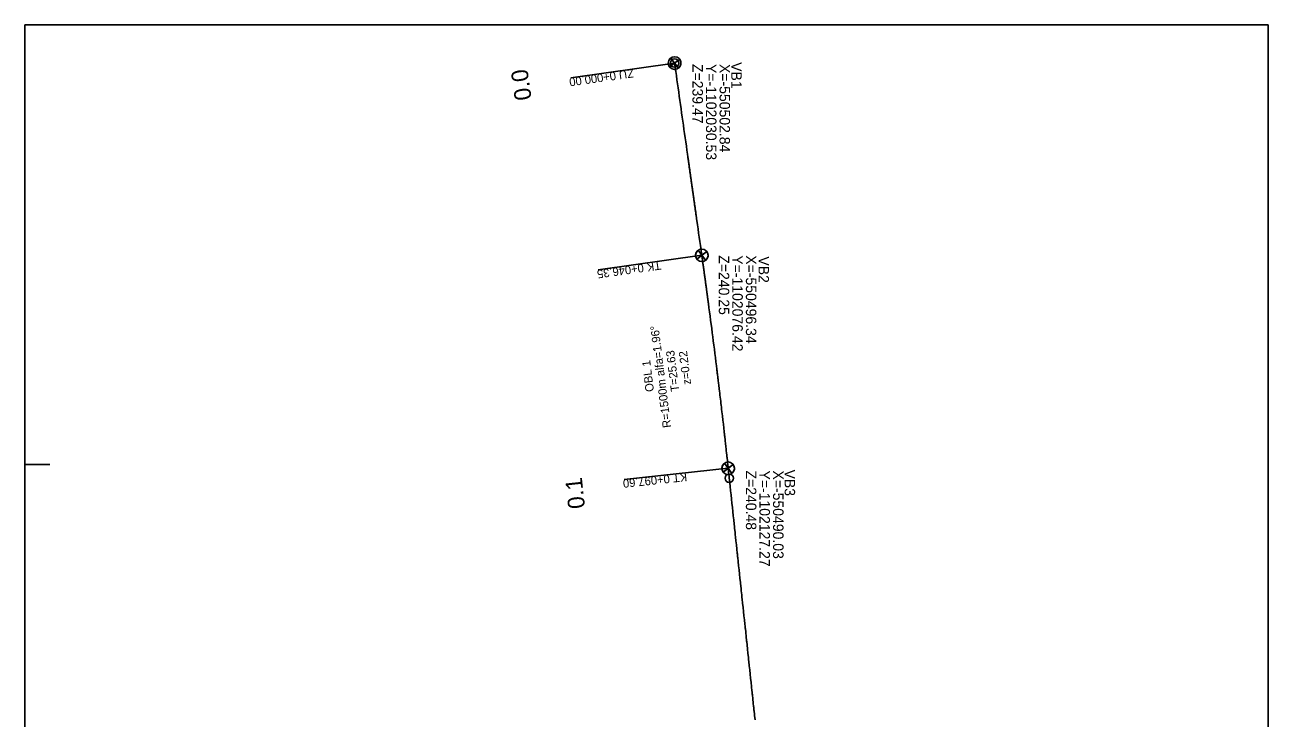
# Model space of a CAD drawing. Extents: x -583517 to -548566, y -1166112 to -1101582.
# Drawn here: x -550658.1 to -550361.1, y -1102186.9 to -1102021.4 of the extents above; entities that cross this region are included whole.
import ezdxf

# ---------------------------------------------------------------- set-up
doc = ezdxf.new("R2010")
doc.units = 0
for name, color, linetype in [('13', 7, 'Continuous'), ('59', 7, 'Continuous'), ('8', 7, 'Continuous'), ('Body pricny rez', 7, 'Continuous'), ('Popis PP', 7, 'Continuous'), ('Rámy', 7, 'Continuous')]:
    doc.layers.add(name, color=color, linetype=linetype)

msp = doc.modelspace()

# ---------------------------------------------------------------- linework, layer by layer
at = {"layer": '13'}
for points in [[(-550502.84, -1102030.53), (-550527.59, -1102034.03)], [(-550496.34, -1102076.42), (-550521.1, -1102079.92)], [(-550490.03, -1102127.27), (-550514.89, -1102129.93)]]:
    msp.add_lwpolyline(points, dxfattribs=at)
at = {"layer": '8'}
for p, q in [((-550501.63, -1102029.63), (-550504.04, -1102031.42)), ((-550503.73, -1102029.32), (-550501.94, -1102031.73)), ((-550502.84, -1102030.53), (-550503.73, -1102029.32)), ((-550502.84, -1102030.53), (-550503.73, -1102029.32)), ((-550501.63, -1102029.63), (-550502.84, -1102030.53)), ((-550504.04, -1102031.42), (-550502.84, -1102030.53)), ((-550504.04, -1102031.42), (-550502.84, -1102030.53)), ((-550502.84, -1102030.53), (-550501.94, -1102031.73)), ((-550495.14, -1102075.52), (-550497.55, -1102077.31)), ((-550497.55, -1102077.31), (-550496.34, -1102076.42)), ((-550497.55, -1102077.31), (-550496.34, -1102076.42)), ((-550496.34, -1102076.42), (-550497.24, -1102075.21)), ((-550496.34, -1102076.42), (-550497.24, -1102075.21)), ((-550497.24, -1102075.22), (-550495.45, -1102077.62)), ((-550495.14, -1102075.52), (-550496.34, -1102076.42)), ((-550496.34, -1102076.42), (-550495.45, -1102077.62)), ((-550491.24, -1102128.17), (-550490.03, -1102127.27)), ((-550491.24, -1102128.17), (-550490.03, -1102127.27)), ((-550488.83, -1102126.38), (-550491.23, -1102128.17)), ((-550490.93, -1102126.07), (-550489.14, -1102128.48)), ((-550490.03, -1102127.27), (-550490.93, -1102126.07)), ((-550490.03, -1102127.27), (-550490.93, -1102126.07)), ((-550488.83, -1102126.38), (-550490.03, -1102127.27)), ((-550490.03, -1102127.27), (-550489.14, -1102128.48))]:
    msp.add_line(p, q, dxfattribs=at)
for centre in [(-550502.84, -1102030.53), (-550496.34, -1102076.42), (-550490.03, -1102127.27)]:
    msp.add_circle(centre, 1.5, dxfattribs=at)
for centre, start, end in [((-550502.84, -1102030.53), 126.6271, 216.6271), ((-550502.84, -1102030.53), 126.6271, 216.6271), ((-550502.84, -1102030.53), 306.6271, 36.6271), ((-550496.34, -1102076.42), 126.6271, 216.6271), ((-550496.34, -1102076.42), 126.6271, 216.6271), ((-550496.34, -1102076.42), 306.6271, 36.6271), ((-550490.03, -1102127.27), 126.6271, 216.6271), ((-550490.03, -1102127.27), 126.6271, 216.6271), ((-550490.03, -1102127.27), 306.6271, 36.6271)]:
    msp.add_arc(centre, 1.5, start, end, dxfattribs=at)
at = {"layer": 'Body pricny rez'}
msp.add_lwpolyline([(-550502.84, -1102030.53), (-550502.7, -1102031.52), (-550502.56, -1102032.51), (-550502.42, -1102033.5), (-550502.28, -1102034.49), (-550502.14, -1102035.48), (-550502, -1102036.47), (-550501.86, -1102037.46), (-550501.72, -1102038.45), (-550501.72, -1102038.45), (-550501.58, -1102039.44), (-550501.44, -1102040.43), (-550501.3, -1102041.42), (-550501.16, -1102042.41), (-550501.02, -1102043.4), (-550500.88, -1102044.39), (-550500.74, -1102045.38), (-550500.6, -1102046.37), (-550500.46, -1102047.36), (-550500.32, -1102048.35), (-550500.17, -1102049.34), (-550500.03, -1102050.33), (-550499.89, -1102051.32), (-550499.75, -1102052.31), (-550499.67, -1102052.88), (-550499.64, -1102053.1), (-550499.61, -1102053.3), (-550499.61, -1102053.33), (-550499.58, -1102053.55), (-550499.55, -1102053.78), (-550499.52, -1102054), (-550499.48, -1102054.23), (-550499.47, -1102054.29), (-550499.45, -1102054.45), (-550499.42, -1102054.68), (-550499.39, -1102054.9), (-550499.36, -1102055.13), (-550499.33, -1102055.28), (-550499.32, -1102055.35), (-550499.29, -1102055.58), (-550499.26, -1102055.8), (-550499.23, -1102056.03), (-550499.2, -1102056.25), (-550499.19, -1102056.27), (-550499.16, -1102056.48), (-550499.13, -1102056.7), (-550499.1, -1102056.93), (-550499.07, -1102057.15), (-550499.05, -1102057.26), (-550499.04, -1102057.38), (-550499.01, -1102057.6), (-550498.97, -1102057.83), (-550498.94, -1102058.05), (-550498.91, -1102058.25), (-550498.91, -1102058.28), (-550498.88, -1102058.5), (-550498.85, -1102058.72), (-550498.81, -1102058.95), (-550498.78, -1102059.17), (-550498.77, -1102059.24), (-550498.75, -1102059.4), (-550498.72, -1102059.62), (-550498.69, -1102059.85), (-550498.66, -1102060.07), (-550498.63, -1102060.23), (-550498.62, -1102060.3), (-550498.59, -1102060.52), (-550498.56, -1102060.75), (-550498.53, -1102060.97), (-550498.5, -1102061.2), (-550498.49, -1102061.22), (-550498.46, -1102061.42), (-550498.43, -1102061.65), (-550498.4, -1102061.87), (-550498.37, -1102062.1), (-550498.35, -1102062.21), (-550498.34, -1102062.32), (-550498.31, -1102062.55), (-550498.27, -1102062.77), (-550498.24, -1102063), (-550498.21, -1102063.2), (-550498.21, -1102063.22), (-550498.18, -1102063.45), (-550498.15, -1102063.67), (-550498.11, -1102063.9), (-550498.08, -1102064.12), (-550498.07, -1102064.19), (-550498.05, -1102064.35), (-550498.02, -1102064.57), (-550497.99, -1102064.8), (-550497.96, -1102065.02), (-550497.93, -1102065.18), (-550497.92, -1102065.25), (-550497.89, -1102065.47), (-550497.86, -1102065.7), (-550497.83, -1102065.92), (-550497.8, -1102066.15), (-550497.79, -1102066.17), (-550497.76, -1102066.37), (-550497.73, -1102066.6), (-550497.7, -1102066.82), (-550497.67, -1102067.05), (-550497.65, -1102067.16), (-550497.64, -1102067.27), (-550497.61, -1102067.5), (-550497.57, -1102067.72), (-550497.51, -1102068.15), (-550497.37, -1102069.14), (-550497.23, -1102070.13), (-550497.09, -1102071.12), (-550496.95, -1102072.11), (-550496.81, -1102073.1), (-550496.67, -1102074.09), (-550496.53, -1102075.08), (-550496.39, -1102076.07), (-550496.34, -1102076.42), (-550496.31, -1102076.68), (-550496.28, -1102076.85), (-550496.26, -1102077.03), (-550496.25, -1102077.06), (-550496.23, -1102077.21), (-550496.21, -1102077.38), (-550496.18, -1102077.56), (-550496.16, -1102077.74), (-550496.13, -1102077.91), (-550496.11, -1102078.05), (-550496.11, -1102078.09), (-550496.08, -1102078.27), (-550496.06, -1102078.44), (-550496.03, -1102078.62), (-550496.01, -1102078.8), (-550495.98, -1102078.98), (-550495.97, -1102079.04), (-550495.96, -1102079.15), (-550495.93, -1102079.33), (-550495.91, -1102079.51), (-550495.88, -1102079.68), (-550495.86, -1102079.86), (-550495.84, -1102080.03), (-550495.84, -1102080.04), (-550495.81, -1102080.21), (-550495.79, -1102080.39), (-550495.76, -1102080.57), (-550495.74, -1102080.74), (-550495.71, -1102080.92), (-550495.7, -1102081.02), (-550495.69, -1102081.1), (-550495.66, -1102081.28), (-550495.64, -1102081.45), (-550495.62, -1102081.63), (-550495.59, -1102081.81), (-550495.57, -1102081.98), (-550495.56, -1102082.01), (-550495.54, -1102082.16), (-550495.52, -1102082.34), (-550495.49, -1102082.51), (-550495.47, -1102082.69), (-550495.44, -1102082.87), (-550495.43, -1102083.01), (-550495.42, -1102083.05), (-550495.4, -1102083.22), (-550495.37, -1102083.4), (-550495.35, -1102083.58), (-550495.32, -1102083.75), (-550495.3, -1102083.93), (-550495.29, -1102084), (-550495.28, -1102084.11), (-550495.25, -1102084.28), (-550495.23, -1102084.46), (-550495.2, -1102084.64), (-550495.18, -1102084.82), (-550495.17, -1102084.88), (-550495.16, -1102084.99), (-550495.16, -1102084.99), (-550495.13, -1102085.17), (-550495.11, -1102085.35), (-550495.08, -1102085.52), (-550495.06, -1102085.7), (-550495.04, -1102085.88), (-550495.02, -1102085.98), (-550495.01, -1102086.05), (-550494.99, -1102086.23), (-550494.96, -1102086.41), (-550494.94, -1102086.59), (-550494.92, -1102086.76), (-550494.89, -1102086.94), (-550494.89, -1102086.97), (-550494.87, -1102087.12), (-550494.84, -1102087.29), (-550494.82, -1102087.47), (-550494.8, -1102087.65), (-550494.77, -1102087.83), (-550494.76, -1102087.96), (-550494.62, -1102088.95), (-550494.49, -1102089.94), (-550494.36, -1102090.93), (-550494.23, -1102091.93), (-550494.1, -1102092.92), (-550494.05, -1102093.35), (-550493.97, -1102093.91), (-550493.84, -1102094.9), (-550493.72, -1102095.89), (-550493.59, -1102096.88), (-550493.46, -1102097.88), (-550493.34, -1102098.87), (-550493.21, -1102099.86), (-550493.09, -1102100.85), (-550492.97, -1102101.82), (-550492.97, -1102101.85), (-550492.84, -1102102.84), (-550492.75, -1102103.59), (-550492.75, -1102103.63), (-550492.72, -1102103.83), (-550492.69, -1102104.07), (-550492.63, -1102104.55), (-550492.6, -1102104.82), (-550492.58, -1102105.02), (-550492.54, -1102105.35), (-550492.52, -1102105.5), (-550492.48, -1102105.82), (-550492.46, -1102105.98), (-550492.45, -1102106.06), (-550492.4, -1102106.46), (-550492.36, -1102106.81), (-550492.34, -1102106.93), (-550492.29, -1102107.41), (-550492.24, -1102107.8), (-550492.23, -1102107.89), (-550492.17, -1102108.37), (-550492.12, -1102108.79), (-550492.11, -1102108.84), (-550492.06, -1102109.32), (-550492, -1102109.79), (-550492, -1102109.8), (-550491.94, -1102110.28), (-550491.94, -1102110.3), (-550491.89, -1102110.76), (-550491.89, -1102110.78), (-550491.83, -1102111.23), (-550491.78, -1102111.71), (-550491.77, -1102111.77), (-550491.72, -1102112.19), (-550491.66, -1102112.67), (-550491.65, -1102112.77), (-550491.61, -1102113.15), (-550491.54, -1102113.76), (-550491.42, -1102114.75), (-550491.31, -1102115.75), (-550491.19, -1102116.74), (-550491.08, -1102117.73), (-550490.99, -1102118.5), (-550490.97, -1102118.73), (-550490.96, -1102118.78), (-550490.94, -1102118.96), (-550490.94, -1102119), (-550490.93, -1102119.08), (-550490.91, -1102119.26), (-550490.89, -1102119.43), (-550490.86, -1102119.72), (-550490.84, -1102119.89), (-550490.79, -1102120.35), (-550490.75, -1102120.71), (-550490.74, -1102120.81), (-550490.68, -1102121.27), (-550490.64, -1102121.71), (-550490.63, -1102121.73), (-550490.58, -1102122.19), (-550490.53, -1102122.66), (-550490.53, -1102122.7), (-550490.48, -1102123.12), (-550490.43, -1102123.58), (-550490.42, -1102123.7), (-550490.38, -1102124.04), (-550490.33, -1102124.5), (-550490.31, -1102124.69), (-550490.28, -1102124.96), (-550490.24, -1102125.36), (-550490.23, -1102125.4), (-550490.23, -1102125.42), (-550490.2, -1102125.69), (-550490.18, -1102125.89), (-550490.13, -1102126.35), (-550490.09, -1102126.68), (-550490.08, -1102126.81), (-550490.03, -1102127.27), (-550490.03, -1102127.27), (-550489.99, -1102127.67), (-550489.98, -1102127.73), (-550489.93, -1102128.19), (-550489.88, -1102128.66), (-550489.88, -1102128.67), (-550489.83, -1102129.12), (-550489.78, -1102129.58), (-550489.78, -1102129.66), (-550489.74, -1102130.04), (-550489.69, -1102130.5), (-550489.67, -1102130.66), (-550489.64, -1102130.96), (-550489.59, -1102131.42), (-550489.56, -1102131.65), (-550489.54, -1102131.89), (-550489.49, -1102132.35), (-550489.46, -1102132.65), (-550489.35, -1102133.64), (-550489.24, -1102134.63), (-550489.14, -1102135.63), (-550489.03, -1102136.62), (-550488.93, -1102137.62), (-550488.82, -1102138.61), (-550488.71, -1102139.61), (-550488.61, -1102140.6), (-550488.54, -1102141.21), (-550488.5, -1102141.59), (-550488.4, -1102142.59), (-550488.33, -1102143.21), (-550488.29, -1102143.58), (-550488.26, -1102143.87), (-550488.2, -1102144.41), (-550488.18, -1102144.58), (-550488.08, -1102145.57), (-550487.97, -1102146.57), (-550487.86, -1102147.56), (-550487.86, -1102147.56), (-550487.86, -1102147.57), (-550487.84, -1102147.76), (-550487.78, -1102148.39), (-550487.76, -1102148.55), (-550487.65, -1102149.55), (-550487.55, -1102150.54), (-550487.44, -1102151.54), (-550487.33, -1102152.53), (-550487.23, -1102153.53), (-550487.12, -1102154.52), (-550487.09, -1102154.82), (-550487.03, -1102155.37), (-550487.01, -1102155.52), (-550486.97, -1102155.92), (-550486.91, -1102156.48), (-550486.91, -1102156.51), (-550486.85, -1102157.03), (-550486.8, -1102157.5), (-550486.79, -1102157.58), (-550486.74, -1102158.13), (-550486.7, -1102158.5), (-550486.59, -1102159.49), (-550486.48, -1102160.49), (-550486.38, -1102161.48), (-550486.27, -1102162.48), (-550486.17, -1102163.47), (-550486.06, -1102164.46), (-550486.01, -1102164.97), (-550485.97, -1102165.27), (-550485.96, -1102165.35), (-550485.95, -1102165.46), (-550485.94, -1102165.59), (-550485.86, -1102166.36), (-550485.85, -1102166.45), (-550485.74, -1102167.45), (-550485.63, -1102168.44), (-550485.6, -1102168.73), (-550485.53, -1102169.44), (-550485.42, -1102170.43), (-550485.32, -1102171.42), (-550485.21, -1102172.42), (-550485.15, -1102173), (-550485.1, -1102173.41), (-550485, -1102174.41), (-550484.89, -1102175.4), (-550484.78, -1102176.4), (-550484.68, -1102177.39), (-550484.57, -1102178.39), (-550484.47, -1102179.38), (-550484.45, -1102179.51), (-550484.36, -1102180.37), (-550484.32, -1102180.74), (-550484.28, -1102181.09), (-550484.25, -1102181.37), (-550484.15, -1102182.36), (-550484.04, -1102183.36), (-550483.96, -1102184.12), (-550483.93, -1102184.35), (-550483.92, -1102184.51), (-550483.88, -1102184.87), (-550483.87, -1102184.99), (-550483.85, -1102185.15), (-550483.83, -1102185.35), (-550483.77, -1102185.92), (-550483.72, -1102186.34), (-550483.62, -1102187.33)], dxfattribs=at)
for centre in [(-550502.84, -1102030.53), (-550489.78, -1102129.66)]:
    msp.add_circle(centre, 1, dxfattribs=at)
at = {"layer": 'Popis PP'}
msp.add_line((-550658.05, -1102126.4), (-550652.05, -1102126.4), dxfattribs=at)
at = {"layer": 'Rámy'}
msp.add_lwpolyline([(-550658.05, -1102021.4), (-550658.05, -1102756.4), (-550361.05, -1102756.4), (-550361.05, -1102021.4)], close=True, dxfattribs=at)

# ---------------------------------------------------------------- texts
at = {"layer": '13'}
for s, height, rotation, p in [('0.0', 4, 98.054, (-550536.97, -1102039.14)), ('ZU 0+000.00', 2, 188.054, (-550512.74, -1102031.93)), ('TK 0+046.35', 2, 188.054, (-550506.24, -1102077.82)), ('R=1500m alfa=1.96%%d', 2, 97.0753, (-550503.66, -1102117.49)), ('OBL 1', 2, 97.0753, (-550507.75, -1102108.9)), ('  T=25.63', 2, 97.0753, (-550501.53, -1102110.32)), ('   z=0.22', 2, 97.0753, (-550498.62, -1102109.4)), ('KT 0+097.60', 2, 186.0965, (-550499.97, -1102128.33)), ('0.1', 4, 96.0965, (-550524.22, -1102136.73))]:
    msp.add_text(s, height=height, rotation=rotation, dxfattribs=at).set_placement(p)
at = {"layer": '59'}
for s, p in [('VB1', (-550489.31, -1102030.3)), ('Z=239.47', (-550498.57, -1102030.74)), ('Y=-1102030.53', (-550495.34, -1102030.74)), ('X=-550502.84', (-550492.1, -1102030.74)), ('Z=240.25', (-550492.28, -1102076.42)), ('Y=-1102076.42', (-550489.05, -1102076.42)), ('X=-550496.34', (-550485.81, -1102076.42)), ('VB2', (-550482.79, -1102076.68)), ('Z=240.48', (-550485.8, -1102127.8)), ('Y=-1102127.27', (-550482.56, -1102127.8)), ('X=-550490.03', (-550479.32, -1102127.8)), ('VB3', (-550476.55, -1102127.58))]:
    msp.add_text(s, height=2.5, rotation=270, dxfattribs=at).set_placement(p)

doc.saveas('drawing.dxf')
